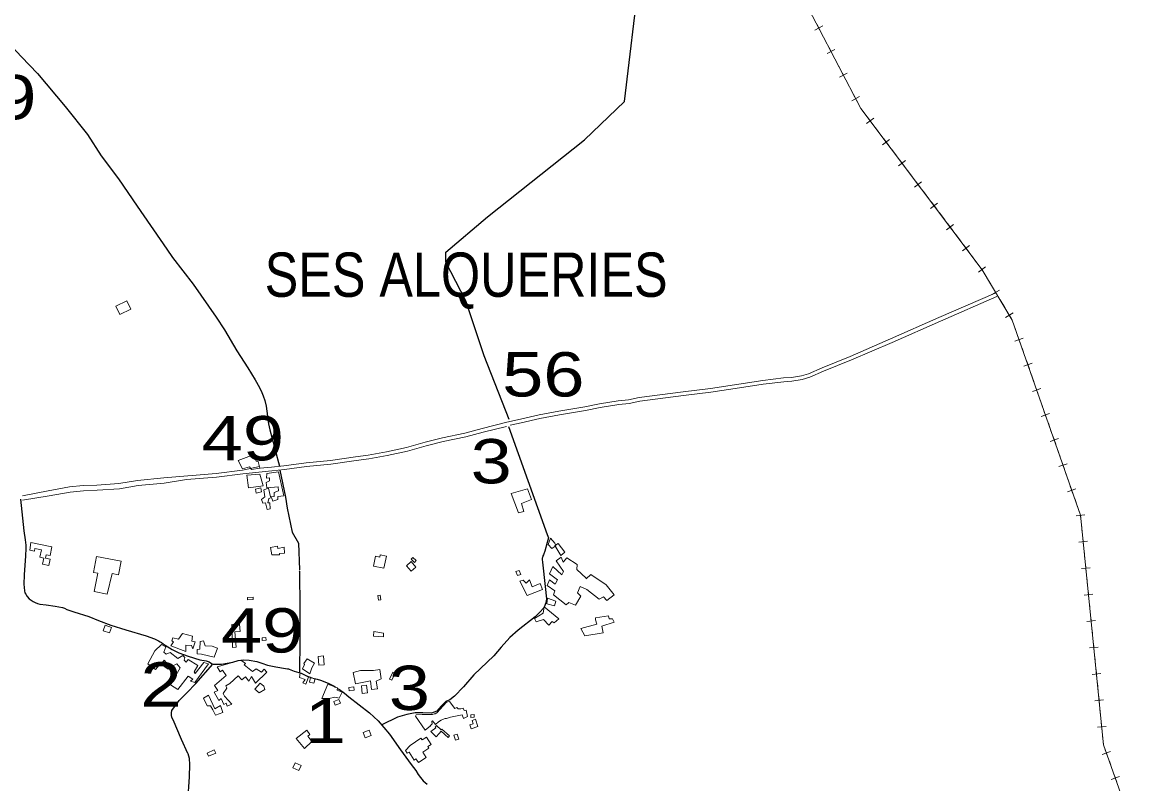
# Model space of a CAD drawing. Extents: x 476989 to 498418, y 4381813 to 4416555.
# Drawn here: x 486413 to 487660, y 4387137 to 4387996 of the extents above; entities that cross this region are included whole.
import ezdxf
from ezdxf.enums import TextEntityAlignment as Align

# ---------------------------------------------------------------- set-up
doc = ezdxf.new("R2010")
doc.units = 0
doc.header["$LTSCALE"] = 20
doc.linetypes.add('MEDIUM_DASHED', pattern=[4.5, 3, -1.5])
for name, color, linetype, lineweight in [('13', 7, 'Continuous', 13), ('34', 7, 'Continuous', 13), ('36', 7, 'Continuous', 13), ('47', 7, 'Continuous', 13), ('48', 7, 'MEDIUM_DASHED', 13), ('6', 7, 'Continuous', 25)]:
    doc.layers.add(name, color=color, linetype=linetype, lineweight=lineweight)
doc.layers.add('7', color=7, linetype='Continuous')

msp = doc.modelspace()

# ---------------------------------------------------------------- linework, layer by layer
at = {"layer": '34'}
for p, q in [((487316.95, 4387992.13), (487308.09, 4387987.49)), ((487310.21, 4387994.24), (487314.84, 4387985.38)), ((487317.16, 4387980.95), (487321.79, 4387972.09)), ((487324.1, 4387967.67), (487328.73, 4387958.8)), ((487330.85, 4387965.55), (487321.99, 4387960.92)), ((487331.05, 4387954.37), (487335.68, 4387945.51)), ((487344.74, 4387938.97), (487335.88, 4387934.34)), ((487338, 4387941.09), (487342.63, 4387932.23)), ((487344.95, 4387927.8), (487349.58, 4387918.93)), ((487358.64, 4387912.4), (487349.78, 4387907.76)), ((487351.89, 4387914.51), (487356.52, 4387905.65)), ((487374.51, 4387888.04), (487366.52, 4387882.02)), ((487367.51, 4387889.02), (487373.52, 4387881.03)), ((487376.53, 4387877.04), (487382.54, 4387869.05)), ((487392.55, 4387864.08), (487384.56, 4387858.06)), ((487385.55, 4387865.06), (487391.56, 4387857.07)), ((487394.57, 4387853.08), (487400.58, 4387845.09)), ((487410.58, 4387840.12), (487402.59, 4387834.1)), ((487403.58, 4387841.1), (487409.6, 4387833.11)), ((487412.6, 4387829.12), (487418.62, 4387821.13)), ((487421.62, 4387817.14), (487427.63, 4387809.15)), ((487428.62, 4387816.16), (487420.63, 4387810.14)), ((487430.64, 4387805.16), (487436.65, 4387797.17)), ((487446.66, 4387792.19), (487438.67, 4387786.18)), ((487439.65, 4387793.18), (487445.67, 4387785.19)), ((487448.67, 4387781.2), (487454.69, 4387773.21)), ((487464.69, 4387768.23), (487456.7, 4387762.22)), ((487457.69, 4387769.22), (487463.7, 4387761.23)), ((487466.71, 4387757.24), (487472.72, 4387749.25)), ((487482.73, 4387744.27), (487474.74, 4387738.26)), ((487475.73, 4387745.26), (487481.74, 4387737.27)), ((487484.75, 4387733.28), (487490.76, 4387725.29)), ((487500.76, 4387720.31), (487492.77, 4387714.3)), ((487501.93, 4387708.74), (487507.05, 4387700.15)), ((487516.46, 4387694.14), (487507.87, 4387689.01)), ((487509.61, 4387695.87), (487514.73, 4387687.28)), ((487517.29, 4387682.99), (487522.41, 4387674.4)), ((487531.82, 4387668.38), (487523.24, 4387663.26)), ((487524.97, 4387670.11), (487530.09, 4387661.52)), ((487532.07, 4387656.96), (487535.37, 4387647.52)), ((487537.02, 4387642.81), (487540.32, 4387633.37)), ((487543.39, 4387639.74), (487533.95, 4387636.44)), ((487541.97, 4387628.65), (487545.28, 4387619.21)), ((487553.3, 4387611.43), (487543.86, 4387608.13)), ((487546.92, 4387614.5), (487550.23, 4387605.06)), ((487551.88, 4387600.34), (487555.18, 4387590.9)), ((487563.2, 4387583.13), (487553.76, 4387579.82)), ((487556.83, 4387586.19), (487560.14, 4387576.76)), ((487561.79, 4387572.04), (487565.09, 4387562.6)), ((487573.11, 4387554.82), (487563.67, 4387551.52)), ((487566.74, 4387557.89), (487570.04, 4387548.45)), ((487571.69, 4387543.73), (487575, 4387534.29)), ((487583.02, 4387526.51), (487573.58, 4387523.21)), ((487576.65, 4387529.58), (487579.95, 4387520.14)), ((487581.6, 4387515.42), (487584.91, 4387505.99)), ((487592.92, 4387498.21), (487583.49, 4387494.9)), ((487586.55, 4387501.28), (487589.86, 4387491.84)), ((487591.51, 4387487.12), (487594.81, 4387477.68)), ((487602.83, 4387469.9), (487593.39, 4387466.6)), ((487596.46, 4387472.97), (487599.76, 4387463.53)), ((487601.42, 4387458.81), (487604.72, 4387449.37)), ((487612.98, 4387440.44), (487603.03, 4387439.44)), ((487609, 4387429.99), (487610, 4387420.04)), ((487615.98, 4387410.6), (487606.03, 4387409.6)), ((487610.5, 4387415.08), (487611.5, 4387405.13)), ((487612, 4387400.15), (487613, 4387390.2)), ((487618.97, 4387380.76), (487609.02, 4387379.76)), ((487613.5, 4387385.24), (487614.5, 4387375.29)), ((487615, 4387370.31), (487615.99, 4387360.36)), ((487616.49, 4387355.4), (487617.49, 4387345.45)), ((487621.97, 4387350.92), (487612.02, 4387349.92)), ((487617.99, 4387340.47), (487618.99, 4387330.52)), ((487624.96, 4387321.08), (487615.01, 4387320.08)), ((487619.49, 4387325.56), (487620.49, 4387315.61)), ((487620.99, 4387310.63), (487621.99, 4387300.68)), ((487622.48, 4387295.72), (487623.48, 4387285.77)), ((487627.96, 4387291.24), (487618.01, 4387290.24)), ((487623.98, 4387280.79), (487624.98, 4387270.84)), ((487630.95, 4387261.4), (487621, 4387260.4)), ((487625.48, 4387265.88), (487626.48, 4387255.93)), ((487626.98, 4387250.95), (487627.98, 4387241)), ((487633.95, 4387231.56), (487624, 4387230.56)), ((487628.48, 4387236.04), (487629.47, 4387226.09)), ((487629.97, 4387221.11), (487630.97, 4387211.16)), ((487631.47, 4387206.2), (487632.47, 4387196.25)), ((487636.95, 4387201.72), (487627, 4387200.72)), ((487632.97, 4387191.27), (487633.97, 4387181.32)), ((487641.94, 4387173.55), (487632.51, 4387170.22)), ((487635.56, 4387176.6), (487638.89, 4387167.17)), ((487640.55, 4387162.46), (487643.89, 4387153.03)), ((487651.93, 4387145.27), (487642.5, 4387141.94)), ((487645.55, 4387148.32), (487648.88, 4387138.89))]:
    msp.add_line(p, q, dxfattribs=at)
for points in [[(486520.9, 4388755.72), (486603, 4388633), (486612, 4388581), (486746, 4388393), (486776, 4388338), (486812, 4388290), (486879, 4388250), (487017, 4388189), (487152, 4388148), (487234, 4388140), (487360, 4387899), (487497, 4387717), (487531, 4387660), (487608, 4387440), (487634, 4387181), (487675, 4387065), (487547, 4387001), (487350, 4386921), (487175, 4386900), (487110, 4386912), (487380, 4386493), (487280.6, 4386441.97)], [(487358.84, 4387901.22), (487360, 4387899), (487364.51, 4387893.01)], [(487493.76, 4387721.3), (487497, 4387717), (487499.36, 4387713.04)], [(487606.37, 4387444.66), (487608, 4387440), (487608.51, 4387434.97)]]:
    msp.add_lwpolyline(points, dxfattribs=at)
at = {"layer": '36'}
for points in [[(486681.81, 4387493.08), (486694.64, 4387494.43), (486708.83, 4387495.72), (486733.93, 4387499.19), (486761.2, 4387501.8), (486789.75, 4387505.79), (486803.91, 4387507.68), (486824.62, 4387511.62), (486847.35, 4387516.42), (486868.27, 4387522.32), (486887.64, 4387527.27), (486913.13, 4387532.74), (486932.76, 4387537.91), (486960.47, 4387544.96), (486975.67, 4387548.51), (486996.79, 4387553.41), (487019.08, 4387557.56), (487048.39, 4387562.31), (487065.1, 4387565.6), (487086.13, 4387569.01), (487097.8, 4387570.4), (487109.95, 4387572.95), (487159.3, 4387579.14), (487190.28, 4387583.2), (487222.47, 4387587.83), (487249.22, 4387591.96), (487272.87, 4387594.88), (487281.57, 4387595.35), (487293.04, 4387597.4), (487301.06, 4387599.65), (487316.2, 4387606.51), (487347.8, 4387619.2), (487393.55, 4387638.93), (487448.21, 4387662.97), (487511.52, 4387690.61)], [(486964.24, 4387541.72), (486976.62, 4387544.44), (486997.64, 4387549.32), (487019.8, 4387553.44), (487049.13, 4387558.2), (487065.84, 4387561.49), (487086.71, 4387564.87), (487098.48, 4387566.27), (487110.55, 4387568.8), (487159.87, 4387575), (487190.84, 4387579.06), (487223.09, 4387583.7), (487249.79, 4387587.82), (487273.23, 4387590.72), (487282.06, 4387591.19), (487293.97, 4387593.33), (487302.49, 4387595.71), (487317.85, 4387602.66), (487349.41, 4387615.35), (487395.22, 4387635.1), (487449.89, 4387659.15), (487513.35, 4387686.84), (487513.66, 4387686.96)], [(486598.9, 4387480.47), (486632.81, 4387482.84), (486662.41, 4387486.84), (486695.05, 4387490.27), (486709.31, 4387491.57), (486734.42, 4387495.04), (486761.69, 4387497.65), (486790.31, 4387501.65), (486804.58, 4387503.55), (486825.44, 4387507.52), (486848.35, 4387512.36), (486869.35, 4387518.28), (486888.6, 4387523.19), (486914.1, 4387528.67), (486933.81, 4387533.87), (486959.88, 4387540.27)], [(486632.38, 4387487), (486661.92, 4387490.99), (486681.28, 4387495)], [(486413.56, 4387461.76), (486442.85, 4387467.63), (486466.63, 4387471.94), (486482.05, 4387473.6), (486497.67, 4387474.12), (486522.37, 4387475.65), (486543.65, 4387479.24), (486573.11, 4387482.2), (486632.38, 4387487)], [(486413.64, 4387456.96), (486443.84, 4387461.83), (486467.47, 4387466.12), (486482.46, 4387467.73), (486497.95, 4387468.25), (486523.04, 4387469.8), (486544.43, 4387473.41), (486573.69, 4387476.35), (486598.9, 4387480.47)]]:
    msp.add_lwpolyline(points, dxfattribs=at)
at = {"layer": '47'}
for points in [[(486681.79, 4387493.07), (486672.16, 4387491.55), (486669.88, 4387494.66), (486662.05, 4387492.45), (486657.31, 4387501.97), (486675.11, 4387508.62), (486677.55, 4387500.93), (486679.72, 4387500.83)], [(486681.77, 4387486.46), (486685.26, 4387473.28), (486668.94, 4387470.89), (486666.9, 4387485.4)], [(486702.81, 4387488.86), (486689.51, 4387486.95), (486689.28, 4387481.93), (486692.44, 4387482.41), (486692.39, 4387478.88), (486688.91, 4387476.98), (486689.65, 4387470.82), (486702.2, 4387472.21), (486702.81, 4387467.63), (486697.75, 4387465.6), (486697.92, 4387461.17), (486693.79, 4387460.93), (486691.37, 4387470.42), (486686.02, 4387468.54), (486687.4, 4387460.65), (486683.39, 4387457.85), (486684.98, 4387453.7), (486687.83, 4387454.11), (486690.05, 4387446.65), (486693.36, 4387447.2), (486693.01, 4387453.96), (486690.46, 4387454.15), (486691.88, 4387458.93), (486694.82, 4387460.09), (486696.34, 4387455.94), (486701.85, 4387457.89), (486701.89, 4387461.04), (486708.65, 4387461.77)], [(486682.82, 4387470.77), (486676.87, 4387469.5), (486677.41, 4387464.84), (486683.66, 4387466.48)], [(486988.11, 4387457.61), (486976.94, 4387453.27), (486979.74, 4387444.23), (486973.64, 4387442.81), (486965.47, 4387464.47), (486983.7, 4387469.68)], [(486423.14, 4387409.21), (486446.93, 4387404.29), (486444.89, 4387394.45), (486440.49, 4387395.32), (486439.77, 4387391.68), (486444.84, 4387390.63), (486443.34, 4387383.4), (486436.27, 4387384.85), (486437.68, 4387391.77), (486433.34, 4387392.62), (486435, 4387401.12), (486427.82, 4387402.49), (486427.27, 4387399.61), (486421.83, 4387400.62)], [(486693.57, 4387403.76), (486695.02, 4387395.26), (486703.65, 4387395.43), (486703.9, 4387397), (486709.38, 4387397.3), (486709.03, 4387403.98), (486701.95, 4387402.51), (486701.39, 4387405.29)], [(487009.7, 4387414.31), (487006.96, 4387406.84), (487011.33, 4387402.58), (487015.65, 4387405.67), (487014.64, 4387408.39)], [(487014.75, 4387405.91), (487021.42, 4387394.48), (487025.9, 4387398.47), (487018.31, 4387407.96)], [(486509.27, 4387351.09), (486494.76, 4387353.93), (486498.79, 4387374.52), (486493.86, 4387375.47), (486497.34, 4387393.57), (486525.22, 4387388.19), (486522.26, 4387372.89), (486514.98, 4387374.26)], [(486821.62, 4387380.39), (486809.87, 4387382.65), (486811.99, 4387393.69), (486816.99, 4387392.71), (486817.49, 4387395.28), (486824.65, 4387393.85)], [(486856.38, 4387386.79), (486852.4, 4387390.34), (486854.28, 4387392.45), (486858.26, 4387388.9)], [(487081.64, 4387350.32), (487072.72, 4387361.63), (487055.18, 4387372.99), (487049.93, 4387368.41), (487049.87, 4387368.86), (487039.57, 4387378.61), (487039.66, 4387384.39), (487028.28, 4387391.83), (487024.09, 4387387.16), (487021.62, 4387392.6), (487016.01, 4387388.56), (487024.24, 4387376.66), (487022.69, 4387372.93), (487012.16, 4387382.01), (487008.44, 4387373.73), (487017.65, 4387367.07), (487014.8, 4387362.09), (487008.57, 4387367.2), (487006, 4387360.86), (487014.77, 4387354.81), (487012.98, 4387350.33), (487027.45, 4387338.79), (487030.26, 4387341.53), (487038.03, 4387338.57), (487043.8, 4387348.84), (487040.32, 4387352.34), (487043.13, 4387359.73), (487050.73, 4387356.09), (487064.68, 4387345.31), (487069.37, 4387347.95), (487073.37, 4387343.84)], [(486852.49, 4387387.75), (486857.88, 4387381.59), (486852.48, 4387376.87), (486847.09, 4387383.03)], [(486970.73, 4387376.37), (486972.49, 4387371.88), (486976.09, 4387373.29), (486974.33, 4387377.78)], [(487000.61, 4387356.21), (486983.33, 4387349.33), (486975.16, 4387365.73), (486978.78, 4387366.8), (486982.1, 4387363.38), (486986.06, 4387367.15), (486988.87, 4387359.23), (486998.08, 4387362.92), (486998.08, 4387362.92)], [(486674.26, 4387344.83), (486667.77, 4387344.47), (486667.62, 4387347.25), (486674.11, 4387347.61)], [(486817.5, 4387349.83), (486818.08, 4387344.44), (486815.47, 4387344.16), (486814.89, 4387349.55)], [(487014.08, 4387337.93), (487005.48, 4387340.08), (487006.17, 4387346.3), (487015.58, 4387343.24)], [(487019.27, 4387323), (487002.58, 4387336.67), (487001.35, 4387329.49), (486991.66, 4387323.47), (486993.71, 4387319.69), (487001.63, 4387322.5), (487007.76, 4387315.81), (487011.43, 4387320.26), (487013.8, 4387318.5)], [(487069.09, 4387307.28), (487048.56, 4387303.82), (487043.88, 4387312.22), (487062.18, 4387316.98), (487060.6, 4387321.96), (487060.63, 4387324.29), (487075.29, 4387326.33), (487076, 4387323.01), (487079.53, 4387323.26), (487081.65, 4387319.41), (487067.7, 4387314.8)], [(486506.97, 4387315.93), (486514.07, 4387313.45), (486511.87, 4387307.16), (486504.77, 4387309.64)], [(486598.24, 4387286.11), (486581.15, 4387292.66), (486583.99, 4387297.05), (486582.13, 4387298.2), (486583.38, 4387301.63), (486589.66, 4387300.12), (486594.18, 4387306.58), (486605.77, 4387303.64), (486604.94, 4387298.1), (486608.67, 4387296.99), (486605.93, 4387289.23), (486604.64, 4387293.07), (486598.12, 4387293.39)], [(486650.75, 4387290.61), (486649.85, 4387316.81), (486657.48, 4387317.36), (486657.49, 4387317.1), (486658.65, 4387317.22), (486659.5, 4387308.99), (486653.39, 4387308.4), (486655.04, 4387291.23)], [(486810.46, 4387308.66), (486821.17, 4387306.93), (486821.18, 4387302.65), (486809.94, 4387303.72)], [(486608.39, 4387251.38), (486623.48, 4387272.54), (486618.24, 4387273.82), (486608.76, 4387261.5), (486607.66, 4387263.32), (486611.75, 4387270.61), (486600.74, 4387277.3), (486598.59, 4387274.33), (486596.07, 4387276.61), (486596.94, 4387279.6), (486594.57, 4387281.59), (486588.97, 4387278.37), (486580.44, 4387285.09), (486575.83, 4387283.21), (486573.24, 4387285.5), (486575.65, 4387291.69), (486570.74, 4387294.09), (486562.91, 4387286.99), (486555.12, 4387272.32), (486563.66, 4387265.97), (486569.91, 4387273.24), (486570.72, 4387272.18), (486573.71, 4387276.63), (486576.14, 4387273.45), (486573.68, 4387269.36), (486578.29, 4387266.36), (486582.32, 4387269.46), (486588.06, 4387272.38), (486591.67, 4387267.67), (486580.81, 4387248.47), (486588.92, 4387243.48), (486600.69, 4387258.61), (486605.82, 4387254.94), (486603.39, 4387252.72)], [(486629.96, 4387279.81), (486615.6, 4387283.24), (486610.81, 4387283.68), (486610.73, 4387288.64), (486613.96, 4387288.96), (486614.39, 4387297.74), (486618.07, 4387298.21), (486620.09, 4387292.55), (486627.82, 4387292.37), (486634.01, 4387290.1)], [(486688.69, 4387298.92), (486684.37, 4387298.62), (486684.15, 4387301.69), (486688.47, 4387301.99)], [(486753.34, 4387281.26), (486754.19, 4387271.17), (486748.31, 4387270.68), (486747.46, 4387280.77)], [(486689.6, 4387262.97), (486676.74, 4387250.7), (486672.05, 4387258.04), (486669.34, 4387252.83), (486665.59, 4387257.68), (486661.19, 4387254.3), (486657.12, 4387258.86), (486647.85, 4387250.21), (486643.31, 4387247.5), (486643.67, 4387246.67), (486644.47, 4387244.86), (486640.18, 4387238.76), (486641.79, 4387236.04), (486650.14, 4387226.99), (486644.78, 4387224.67), (486643.48, 4387227.99), (486641.13, 4387226.44), (486638.15, 4387233.39), (486635.34, 4387231.11), (486630, 4387240.34), (486634.08, 4387242.3), (486630.55, 4387247.83), (486643.47, 4387259.35), (486639.43, 4387265.26), (486636.78, 4387263.35), (486633.33, 4387269.1), (486658.49, 4387275.95), (486661.12, 4387275.83), (486665.28, 4387272.85), (486664.05, 4387271.14), (486673.33, 4387263.73), (486677.42, 4387266.74), (486683.6, 4387262.9), (486686.35, 4387266.39)], [(486738.05, 4387261.15), (486729.72, 4387266.75), (486732.19, 4387271.44), (486731.46, 4387272.57), (486735.21, 4387278.07), (486743.24, 4387273.08), (486740.47, 4387267.87)], [(486727.03, 4387262.13), (486736.71, 4387257.19), (486733.6, 4387249.28), (486730.17, 4387250.98), (486732.78, 4387254.7), (486726.51, 4387257.04)], [(486742.69, 4387250.35), (486737.52, 4387251.81), (486738.96, 4387256.93), (486744.13, 4387255.47)], [(486806.59, 4387253.19), (486789.73, 4387249.68), (486787.14, 4387262.62), (486795.2, 4387264.76), (486809.98, 4387264.77), (486817.05, 4387266.02), (486818.71, 4387255.57), (486813.04, 4387252.65), (486814.34, 4387244.15), (486807.73, 4387243.57)], [(486834.4, 4387261.64), (486830.63, 4387253.99), (486828.15, 4387255.21), (486831.92, 4387262.86)], [(486681.92, 4387250.7), (486675.89, 4387243.58), (486681.01, 4387239.46), (486687.14, 4387243.57), (486685.99, 4387247.04)], [(486758.36, 4387249.45), (486769.41, 4387245.09), (486768.92, 4387242.62), (486774.67, 4387240.36), (486771.04, 4387233.59), (486766.11, 4387234.86), (486759.93, 4387233.15), (486751.53, 4387233.27)], [(486788.28, 4387242.57), (486782.54, 4387241.81), (486782.02, 4387245.74), (486787.76, 4387246.5)], [(486797.31, 4387238.84), (486796.27, 4387247.46), (486802.02, 4387248.15), (486803.06, 4387239.53)], [(486617.97, 4387233.61), (486622.2, 4387225.07), (486626.1, 4387225.01), (486628.51, 4387220.4), (486628.66, 4387220.4), (486631.73, 4387214.42), (486640.02, 4387217.53), (486637.28, 4387225.22), (486630.7, 4387221.57), (486623.57, 4387236.9)], [(486770.8, 4387232.09), (486765.12, 4387229.83), (486766.8, 4387225.62), (486772.48, 4387227.88)], [(486868.22, 4387197.45), (486857.35, 4387213.44), (486858.19, 4387214.78), (486864.88, 4387215.21), (486871.55, 4387215.12), (486876.13, 4387215.27), (486876.51, 4387215.34), (486878.54, 4387215.84), (486879.44, 4387216.05), (486881.26, 4387217), (486892.46, 4387229.22), (486895.77, 4387229.7), (486901.66, 4387221.81), (486904.08, 4387223.13), (486905.64, 4387221.53), (486908.56, 4387221.56), (486910.07, 4387221.92), (486911.05, 4387222.43), (486912.36, 4387219.63), (486914.7, 4387220.2), (486916.17, 4387213.05), (486911.56, 4387210.56), (486910.04, 4387214.71), (486896.95, 4387212.12), (486892.2, 4387210.84), (486891.52, 4387210.63), (486890.92, 4387210.56), (486887.98, 4387209.48), (486886.39, 4387208.75), (486883.29, 4387206.99), (486879.8, 4387203.89), (486876.55, 4387208.06), (486875.64, 4387207.33), (486876.21, 4387204.77), (486873.77, 4387202.48), (486874.07, 4387202.25)], [(486920.17, 4387198.96), (486927.86, 4387201.55), (486925.07, 4387209.82), (486921.31, 4387208.57), (486922.6, 4387204.66), (486918.63, 4387203.36)], [(486919.83, 4387211.95), (486923.66, 4387212.18), (486923.48, 4387215.12), (486919.65, 4387214.89)], [(486740.48, 4387184.58), (486735.69, 4387190.72), (486737.89, 4387192.57), (486734.51, 4387197.57), (486722.74, 4387187.98), (486732.04, 4387176.89)], [(486804.97, 4387197.53), (486807.29, 4387191.65), (486800.49, 4387188.97), (486798.17, 4387194.85)], [(486874.8, 4387195.93), (486880.65, 4387190.07), (486884.2, 4387193.62), (486884.1, 4387193.71), (486886.41, 4387196.28), (486894.11, 4387189.35), (486895.63, 4387191.04), (486887.19, 4387198.61), (486886.47, 4387197.82), (486881.06, 4387202.73), (486879.38, 4387200.88), (486880.32, 4387200.01)], [(486900.71, 4387191.74), (486902.59, 4387186.12), (486906.35, 4387187.38), (486904.47, 4387193)], [(486851.24, 4387180.36), (486863.52, 4387188.59), (486864.92, 4387186.48), (486869.68, 4387189.65), (486875.18, 4387181.39), (486871.42, 4387178.9), (486872.43, 4387177.36), (486865.55, 4387172.85), (486869.53, 4387166.76), (486860.55, 4387160.89), (486857.85, 4387165.01), (486855.95, 4387163.76), (486850.02, 4387172.75), (486847.96, 4387171.41), (486845.86, 4387174.63)], [(486630.19, 4387175.2), (486622.2, 4387171.67), (486623.78, 4387168.09), (486631.77, 4387171.62)], [(486725.45, 4387151.85), (486718.86, 4387154.86), (486721.52, 4387160.69), (486728.11, 4387157.68)]]:
    msp.add_lwpolyline(points, close=True, dxfattribs=at)
at = {"layer": '48'}
msp.add_lwpolyline([(486531.5, 4387681.91), (486518.99, 4387675.77), (486523.62, 4387666.34), (486536.13, 4387672.48)], close=True, dxfattribs=at)
at = {"layer": '6'}
for p, q in [((486704.26, 4387490.71), (486710.68, 4387460.5)), ((486815.26, 4387207.87), (486827.96, 4387192.96))]:
    msp.add_line(p, q, dxfattribs=at)
for points in [[(486963.22, 4387547.94), (486934.94, 4387619.76), (486914.2, 4387682.13), (486891.58, 4387725.6), (486891.58, 4387736.94), (486938.71, 4387776.63), (487048.06, 4387863.56), (487093.3, 4387907.03), (487110.27, 4388048.78), (487117.81, 4388154.62)], [(486383.88, 4387990.09), (486386.63, 4387987.64), (486397.48, 4387973.58), (486412.62, 4387957.15), (486430.7, 4387938.38), (486461.98, 4387901.19), (486486.91, 4387869.73), (486502.64, 4387845.57), (486522.26, 4387819.72), (486543.26, 4387788.72)], [(486543.26, 4387788.72), (486576.47, 4387740.24), (486582.99, 4387730.92)], [(486583.19, 4387730.92), (486606.29, 4387700.79), (486632.5, 4387663.69), (486641.84, 4387649.12), (486655.83, 4387625.66), (486668.23, 4387606.21), (486676.45, 4387592.72), (486681.31, 4387584.19), (486683.88, 4387578.47), (486685.34, 4387574.6), (486687.31, 4387569.4), (486688.59, 4387562.92), (486690.24, 4387551.76), (486691.38, 4387543), (486693, 4387536.2), (486695.64, 4387526.49), (486698.83, 4387513.46), (486703.98, 4387495.26)], [(486962.42, 4387540.27), (487005.9, 4387418.31), (487007.28, 4387414.58), (487005.99, 4387409.23), (487003.38, 4387399.43), (487002.36, 4387396.43), (487001.65, 4387395.16), (487001.2, 4387394.35), (487000.89, 4387393.54), (487000.51, 4387392.28), (487000.42, 4387391.62), (487000.4, 4387390.21), (487000.5, 4387386.99), (487003.86, 4387359.55), (487005.09, 4387345.63), (487004.67, 4387343.51), (487003.95, 4387340.29), (487003.31, 4387338.25), (487002, 4387335.41), (486997.18, 4387330.36), (486992.38, 4387325.46), (486973.32, 4387310.35), (486963.98, 4387301.94), (486954.08, 4387291.21), (486945.75, 4387281.5), (486923.23, 4387259.91), (486911.64, 4387246.42), (486901.28, 4387235.99), (486896.18, 4387231.77)], [(486411.61, 4387458.24), (486415.3, 4387422.43), (486416.72, 4387412.28), (486417.46, 4387406.2), (486417.33, 4387402.54), (486416.99, 4387394.22), (486415.48, 4387372.78), (486415.33, 4387362.26), (486415.97, 4387354.88), (486416.47, 4387352.52), (486417.3, 4387350.83), (486419.05, 4387348.22), (486421.07, 4387345.87), (486425.78, 4387342.62), (486428.02, 4387341.52), (486430.46, 4387340.43), (486433.13, 4387339.5), (486440.42, 4387338.79), (486450.6, 4387337.38), (486458.96, 4387335.83), (486461.08, 4387334.99), (486463.79, 4387333.66), (486471.49, 4387330.85), (486488.68, 4387325.72), (486499.63, 4387321.14), (486513.37, 4387315.84), (486530.49, 4387310.87), (486553.35, 4387303.94), (486562.89, 4387300.43), (486567.35, 4387298.34), (486569.2, 4387297.27), (486570.62, 4387296.51), (486572.68, 4387295.06), (486574.6, 4387293.23)], [(486710.68, 4387460.5), (486712.57, 4387448.03), (486718.24, 4387420.84), (486725.43, 4387408.38), (486726.56, 4387378.54)], [(486726.16, 4387377.24), (486726.32, 4387377.08), (486726.91, 4387334.91), (486726.62, 4387299.12), (486726.56, 4387263.13)], [(486574.6, 4387293.23), (486582.62, 4387288.43), (486590.34, 4387284.71), (486600.7, 4387280.94), (486613.89, 4387276.82), (486621.12, 4387275.61), (486624.29, 4387274.43), (486628.31, 4387271.95)], [(486600.42, 4387116.95), (486602.31, 4387144.73), (486602.51, 4387158.7), (486602.12, 4387165.54), (486600.59, 4387170.92), (486600.46, 4387171.2), (486593.21, 4387186.85), (486583.65, 4387209.28), (486582.41, 4387211.77), (486581.87, 4387214.56), (486581.79, 4387217.25), (486582.34, 4387219.68), (486590.6, 4387230.84), (486599.3, 4387239.8), (486609.37, 4387250.12), (486628.41, 4387272.11)], [(486628.9, 4387272.11), (486638.48, 4387271.93), (486650.95, 4387274.12), (486657.1, 4387276.06), (486663.18, 4387277.02), (486669.74, 4387276.52), (486678.26, 4387275.12), (486683.99, 4387273.21), (486690.31, 4387270.94), (486699.7, 4387269.09), (486710.54, 4387267.04), (486713.02, 4387266.69), (486713.92, 4387266.53), (486714.59, 4387266.16), (486720.23, 4387264.18), (486728.33, 4387261.91), (486734.39, 4387258.65), (486740.44, 4387256.54)], [(486741.42, 4387256.25), (486746.47, 4387255.19), (486749.97, 4387254.04), (486758.67, 4387250.65), (486765.42, 4387247.08), (486766.97, 4387246.15)], [(486769.4, 4387244.7), (486771.63, 4387243.37), (486777.04, 4387239.11), (486782.02, 4387235.2), (486805.26, 4387217.13), (486815.26, 4387207.87)], [(486896.18, 4387231.77), (486891.75, 4387230.01), (486886.29, 4387224.76), (486881.42, 4387219.11), (486875.57, 4387216.78), (486865.44, 4387217.17), (486857.06, 4387216.97), (486847.71, 4387215.22), (486837.18, 4387212.11), (486819.25, 4387203.55)], [(486827.96, 4387192.96), (486840.26, 4387175.44), (486852.39, 4387158.74), (486857.7, 4387152), (486860.52, 4387147.59), (486862.96, 4387144.22), (486865.82, 4387140.44), (486870.56, 4387136.44)]]:
    msp.add_lwpolyline(points, dxfattribs=at)

# ---------------------------------------------------------------- texts
at = {"layer": '13', "width": 1.25}
for s, p in [('3', (486942.77, 4387475.99)), ('49', (486684.21, 4387285.09)), ('2', (486570.08, 4387224.13)), ('3', (486850.42, 4387220.28))]:
    msp.add_text(s, height=50, dxfattribs=at).set_placement(p, align=Align.CENTER)
at = {"layer": '6', "width": 1.25}
for s, p in [('49', (486382.99, 4387886.71)), ('56', (487001.59, 4387574.03)), ('49', (486662.47, 4387501.92)), ('1', (486755.68, 4387182.92))]:
    msp.add_text(s, height=50, dxfattribs=at).set_placement(p, align=Align.CENTER)
at = {"layer": '7', "width": 0.85}
msp.add_text('SES ALQUERIES', height=50, dxfattribs=at).set_placement((486914.49, 4387686.48), align=Align.CENTER)

doc.saveas('drawing.dxf')
